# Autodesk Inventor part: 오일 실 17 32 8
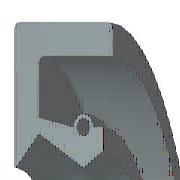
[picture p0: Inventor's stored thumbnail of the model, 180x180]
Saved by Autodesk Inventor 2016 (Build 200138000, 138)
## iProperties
IsCustomPart: 1
Created: 2012-02
Part Number: 오일 실 17 32 8
Material: 고무
Description: 오일-실
Document SubType Name: Modeling
Standard: KS B 2804
Designer: mduedu
Standards Organization: KS
Language: ko-KR
Size Designation: D - 17 32 8
Categories: <MemberInstance><Categories><Category DisplayName="샤프트 부품" InternalName="7f7aeb1f-a693-4053-b835-cee3144e0d98" Mnemonic="SHFT"><Category DisplayName="실링" Intern
Density: 0.93 g/cm^3
Appearance: 고무 - 검은색 - 버전 1.1
Author: mduedu
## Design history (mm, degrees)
revolve "본체" stored, may be unused: angle "d17" = 90 deg
revolve "스프링1" stored, may be unused: angle "d18" = 90 deg
body "Solid1"
sketch "스케치1"
  geometry: L1 (0, 16)-(8, 16); L2 (8, 14.25)-(1.75, 14.25); L3 (1.75, 10.25)-(4.9, 8.5); L4 (4.9, 8.5)-(0, 8.5); L5 (0, 0)-(9.586, 0) reference; L6 (4.9, 8.5)-(6.3, 9.375); L7 (0, 18)-(0, -3) reference; L8 (-1.941, 0)-(11.507, 0) reference; L9 (4.2, 10.6)-(1.75, 11.21); L10 (1.75, 11.21)-(1.75, 14.25); L11 (0, 16)-(0, 8.588); L12 (4.9, 8.5)-(0, 8.5); L13 (1.75, 10.25)-(0.152, 8.528); L14 (8, 16)-(8, 14.25); L15 (5.6, 10.6)-(6.3, 10.6); L16 (6.3, 10.6)-(6.3, 9.375); C1 r 0.455 at (4.9, 10.6); A1 r 0.7 centre (4.9, 10.6) between (5.6, 10.6) and (4.2, 10.6); A2 r 0.088 centre (0.088, 8.588) between (0, 8.588) and (0.152, 8.528); 1 further point
  constraints: 28 end point, 5 horizontal alignment, 5 point on line, 4 point on circle, 4 vertical alignment, 3 centre point, 3 tangent, 2 collinear, 2 horizontal, 2 perpendicular, 1 coincident, 1 parallel
  dimensions: "d0" = 32 diameter of L1 L5 (= SD2); "d1" = 1.75 distance of L1.end L2.start (= SD); "d2" = 0.91 diameter of C1 (= SPDI); "d3" = 1.4 diameter of A1 (= SPDA); "d4" = 17 diameter of L3.end L5 (= NND); "d5" = 20.5 diameter of L3.start L5 (= TKDM); "d7" = 22.42 diameter of L9.end L5 (= TKDM + 0.24 x SWDT); "d8" = 1.75 distance between parallel lines of L11 L10 (= SD); "d9" = 4.9 distance from line of L11 C1.centre (= SPDST); "d10" = 21.2 diameter of C1.centre L5 (= HLDM); "d11" = 0.0875 radius of A2 (= 0.25 x LAB); "d12" = 6.3 distance between parallel lines of L11 L16 (= SDI); "d13" = 18.75 diameter of L6.end L5 (= ABDM); "d14" = 8 distance from line of L11 L1.end (= SWDT)
fillet "모깎기1" dims "d6" = 0.3 (= RR)
other parameters: "SD2" = 32 [user parameter; used in 1 equation term], "SWDT" = 8 [user parameter; used in 2 equation terms], "RR" = 0.3 [user parameter; used in 1 equation term], "SD" = 1.75 [user parameter; used in 2 equation terms], "NND" = 17 [user parameter; used in 1 equation term], "SPDA" = 1.4 [user parameter; used in 1 equation term], "SPDI" = 0.91 [user parameter; used in 1 equation term], "TKDM" = 20.5 [user parameter; used in 2 equation terms], "HLDM" = 21.2 [user parameter; used in 1 equation term], "ABDM" = 18.75 [user parameter; used in 1 equation term], "SDI" = 6.3 [user parameter; used in 1 equation term], "SPDST" = 4.9 [user parameter; used in 1 equation term], "LAB" = 0.35 [user parameter; used in 1 equation term], "d15" = 0, "d16" = 0, "d19" = 0
